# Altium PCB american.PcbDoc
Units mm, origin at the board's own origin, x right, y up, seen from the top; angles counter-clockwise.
Board outline 35 x 24 mm, 2 copper layers (Top Layer, Bottom Layer); 35 components, 19 nets, 74 pads, 16 vias.
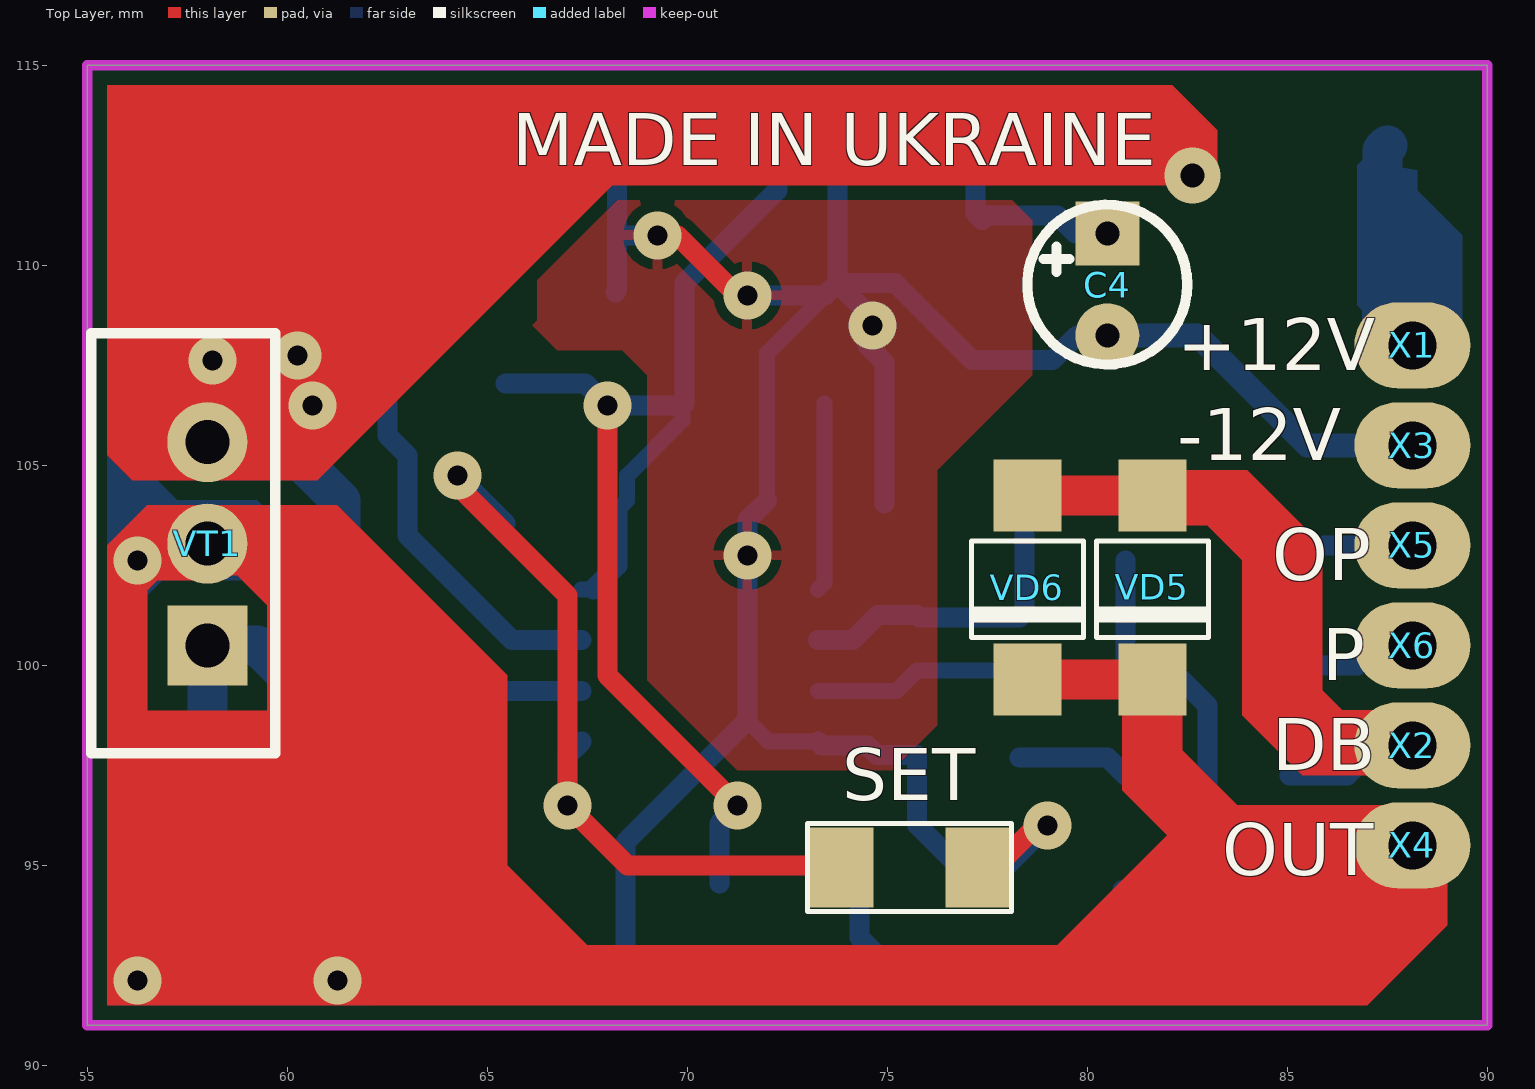
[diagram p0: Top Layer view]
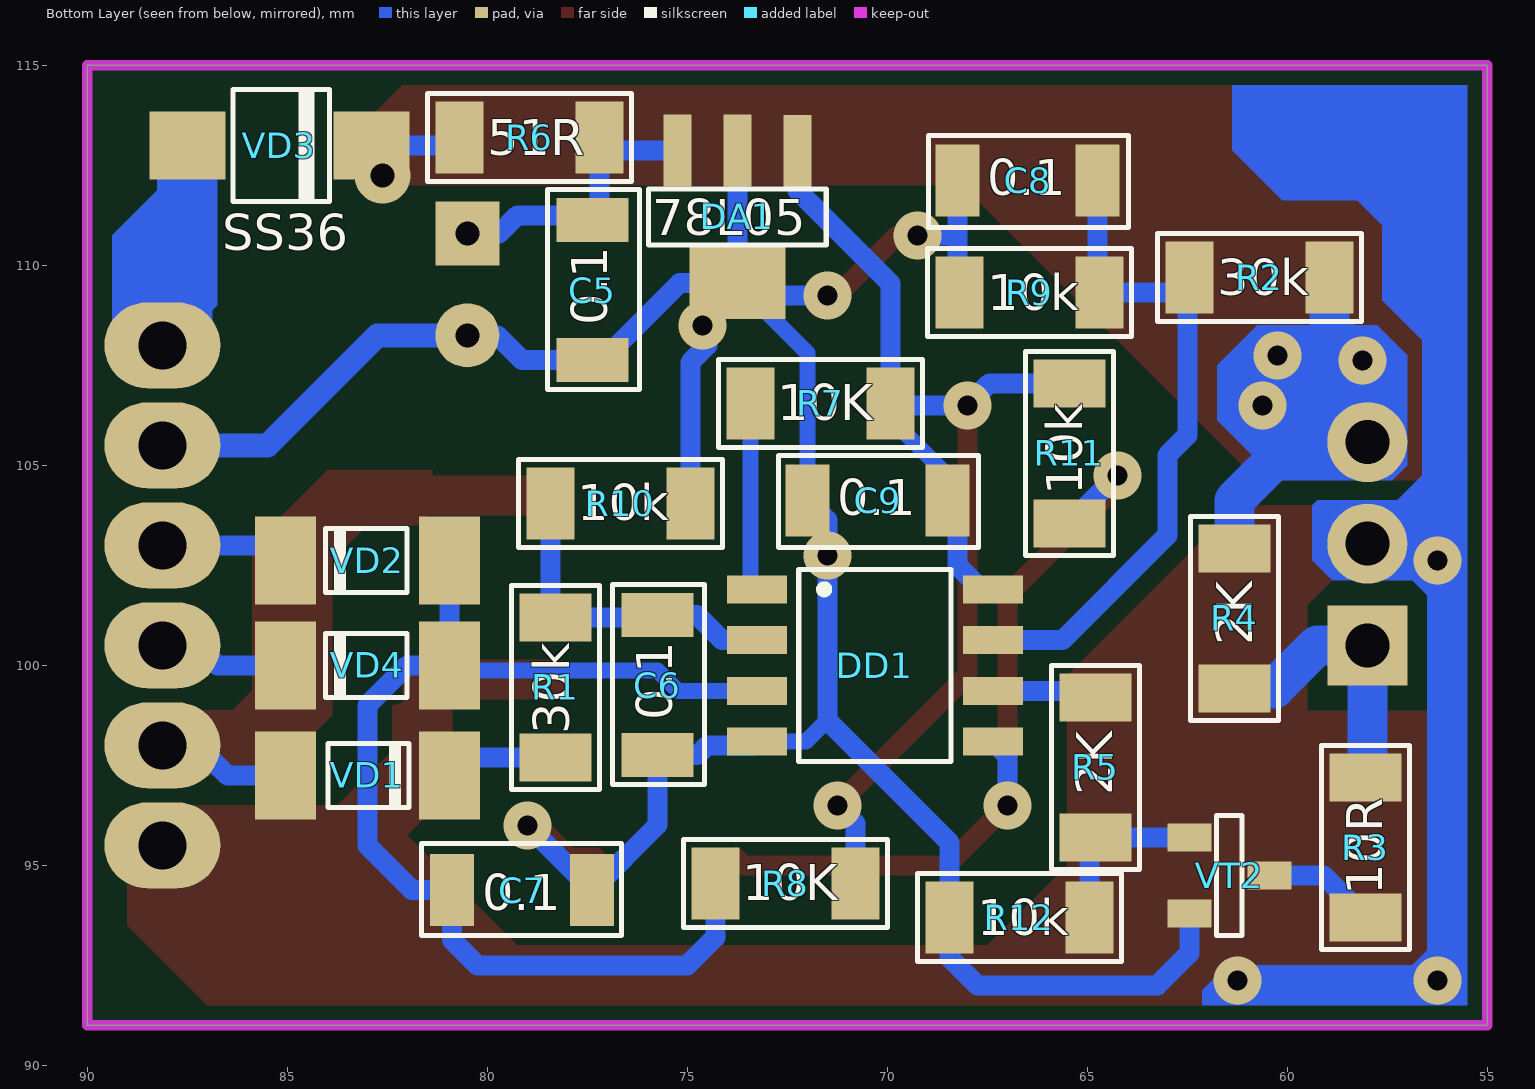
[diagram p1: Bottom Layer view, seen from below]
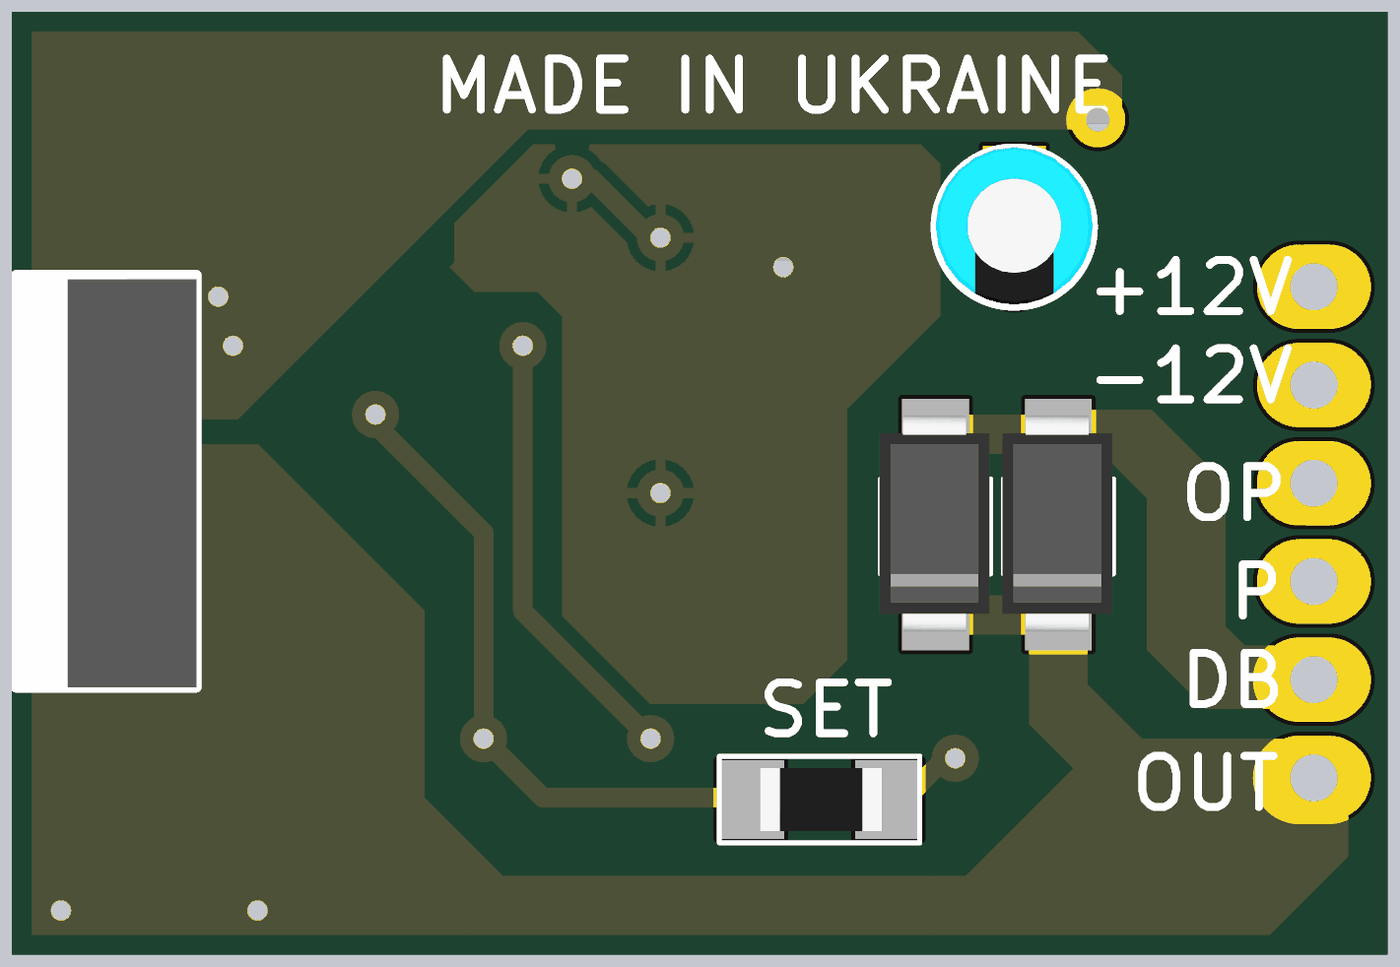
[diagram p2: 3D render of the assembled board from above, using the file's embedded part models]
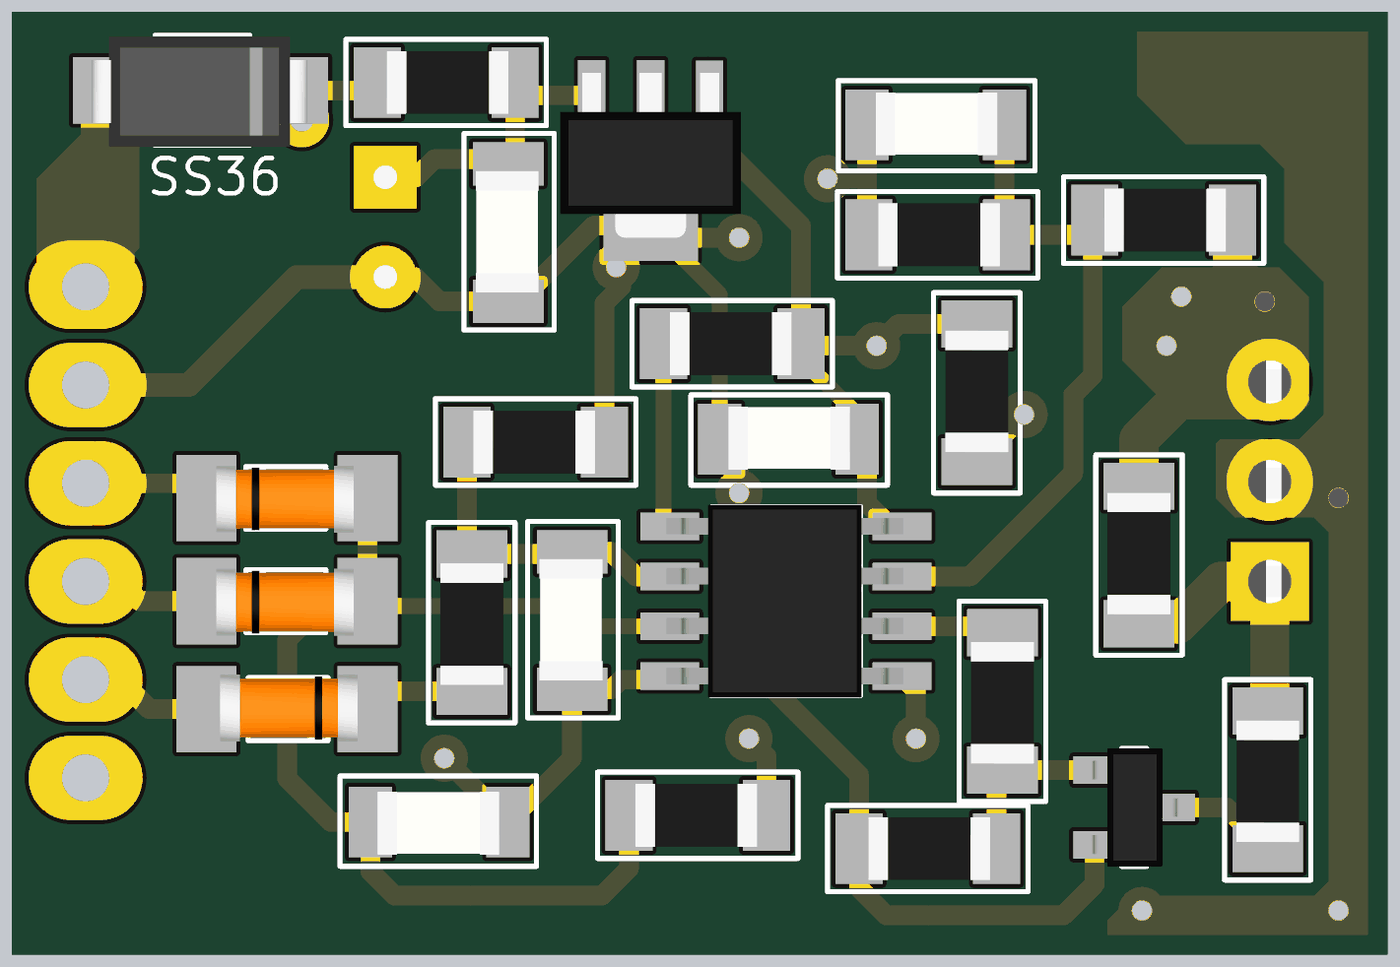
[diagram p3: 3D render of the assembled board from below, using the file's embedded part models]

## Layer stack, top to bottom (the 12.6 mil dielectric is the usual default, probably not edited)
Top Solder: solder mask 0.0102, Solder Resist, Dk 3.5
Top Layer: signal copper 0.0356
Dielectric 1: dielectric 0.32, FR-4, Dk 4.8
Bottom Layer: signal copper 0.0356
Bottom Solder: solder mask 0.0102, Solder Resist, Dk 3.5

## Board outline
55,91 90,91 90,115 55,115

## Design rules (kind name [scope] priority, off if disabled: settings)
Clearance [All] p1: gap=0.254
PolygonConnect [All] p1: connectstyle=Relief reliefconductorwidth=0.254 reliefentries=4 polygonreliefangle="90 Angle" airgapwidth=0.254
RoutingVias [All] p1: holewidth=0.711 width=1.27 viastyle="Through Hole" minholewidth=0.711 minwidth=1.27 maxholewidth=0.711 maxwidth=1.27
SolderMaskExpansion [All] p1: expansion=0.102
Width [All] p1: maxlimit=1 minlimit=0.4 preferedwidth=0.5
29 further rules are at their usual default settings.

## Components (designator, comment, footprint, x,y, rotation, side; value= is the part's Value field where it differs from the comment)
C4 "22.0" 2.54mm 80.5,108.25 r90 top
C5 "0.1" 1206_CAP 78,107.5 r90 bottom
C6 "0.1" 1206_CAP 76.375,97.625 r90 bottom
C7 "0.1" 1206_CAP 77.25,93.75 r0 bottom
C8 "0.1" 1206_CAP 68.375,112.75 r180 bottom
C9 "0.1" 1206_CAP 72.125,104.75 r180 bottom
DA1 "78L05" SOT89 73.75,109.875 r0 bottom
DD1 "ATtiny13A" SO8 72.25,102.5 r180 bottom
R1 "30k" 1206#1 77.5,101 r270 bottom
R2 "30k" 1206#1 62.25,110.5 r180 bottom
R3 "10R" 1206#1 57.25,97 r270 bottom
R4 "2K" 1206#1 62.125,99.625 r90 bottom
R5 "2K" 1206#1 64,99 r270 bottom
R6 "51R" 1206#1 80.5,114 r180 bottom
R7 "10K" 1206#1 70.125,105.75 r0 bottom
R8 "10K" 1206#1 71,93.75 r0 bottom
R9 "10k" 1206#1 68,110.125 r180 bottom
R10 "10k" 1206#1 75.125,103.25 r0 bottom
R11 "10k" 1206#1 66.25,103.75 r90 bottom
R12 "10k" 1206#1 68.25,94.5 r180 bottom
SET "10k" 1206#2 74,95.75 r0 top
VD1 "LL4148" SOD80 84.75,97.25 r180 bottom
VD2 "LL4148" SOD80 81.25,102.625 r0 bottom
VD3 "SS36" SMA(DO-214AC)#1 87.5,113 r180 bottom
VD4 "LL4148" SOD80 81.25,100 r0 bottom
VD5 "SS36" SMA(DO-214AC)#2 81.625,104.25 r270 top
VD6 "SS36" SMA(DO-214AC)#2 78.5,104.25 r270 top
VT1 "IRF9Z34NPBF" TO220 58,100.5 r90 top
VT2 "BC817" SOT23 60.75,94.75 r270 bottom
X1 "CON1" ZL201-1G 88.125,108 r0 top
X2 "CON1" ZL201-1G 88.125,98 r0 top
X3 "CON1" ZL201-1G 88.125,105.5 r0 top
X4 "CON1" ZL201-1G 88.125,95.5 r0 top
X5 "CON1" ZL201-1G 88.125,103 r0 top
X6 "CON1" ZL201-1G 88.125,100.5 r0 top

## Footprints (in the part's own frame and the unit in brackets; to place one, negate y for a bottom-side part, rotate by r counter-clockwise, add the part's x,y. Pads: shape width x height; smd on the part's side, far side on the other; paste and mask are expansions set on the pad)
2.54mm [mm]
  round 1.6 hole 0.6: 1(0,0)
  rect 1.6x1.6 hole 0.6: 2(2.54,0)
  silkscreen extent -0.73,-2 3.27,2, body extent -0.71,-2 3.3,2, height 7.5
1206#1 [mm]
  rect 1.2x1.8 smd: 1(-0.2,-0.8) 2(3.3,-0.8)
  silkscreen extent -1,-1.9 4.1,0.3, body extent 0.04,-1.6 3.14,0, height 0.6
1206#2 [mm]
  rect 1.7x2 smd: 1(-0.2,-0.8) 2(3.3,-0.8)
  silkscreen extent -1,-1.9 4.1,0.3, body extent 0.04,-1.6 3.14,0, height 0.6
1206_CAP [mm]
  rect 1.1x1.8 smd: 1(0.13,-0.628) 2(3.63,-0.628)
  silkscreen extent -0.6,-1.8 4.4,0.5, body extent 0.35,-1.4 3.45,0.2, height 1
SMA(DO-214AC)#1 [mm]
  rect 1.9x1.7 smd: 1(0,0) 2(4.6,0)
  silkscreen extent 1.14,-1.4 3.56,1.4, body extent -0.48,-1.43 5.02,1.37, height 2.31
SMA(DO-214AC)#2 [mm]
  rect 1.8x1.7 smd: 1(0,0) 2(4.6,0)
  silkscreen extent 1.14,-1.4 3.56,1.4, body extent -0.48,-1.43 5.02,1.37, height 2.31
SO8 [mm]
  rect 1.5x0.7 smd: 1(-1.013,-0.6) 2(-1.013,-1.87) 3(-1.013,-3.14) 4(-1.013,-4.41) 5(4.893,-4.41) 6(4.893,-3.14) 7(4.893,-1.87) 8(4.893,-0.6)
  silkscreen extent 0.03,-4.9 3.84,-0.1, body extent -1.1,-4.95 4.93,-0.05, height 1.6
SOD80 [mm]
  rect 1.524x2.2 smd: 1(-0.3,0) 2(3.8,0)
  silkscreen extent 0.76,-0.8 2.79,0.84, body extent 0.05,-0.82 3.55,0.88, height 1.7
SOT23 [mm]
  rect 0.7x1.1 smd: 1(-0.95,-1.7) 2(0.95,-1.7) 3(0,0.3)
  silkscreen extent -1.5,-1.02 1.5,-0.38, body extent -1.5,-2 1.5,0.65, height 1.2
SOT89 [mm]
  rect 0.7x1.8 smd: 1(1.5,-3) 2(0,-3) 3(-1.5,-2.983)
  rect 2.4x1.8 smd: 2(0,0.318)
  silkscreen extent -2.22,-2.03 2.22,-0.64, body extent -2.3,-3.58 2.3,0.63, height 1.6
TO220 [mm]
  rect 2x2 hole 1.1: 1(0,0)
  round 2 hole 1.1: 2(2.54,0) 3(5.08,0)
  silkscreen extent -2.7,-1.7 7.8,2.9, body extent -2.7,-1.7 7.7,2.8, height 18.5
ZL201-1G [mm]
  oval 2.9x2.15 hole 1.2: 1(0,0)

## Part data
C4: library part CAP_POL
C5 C6 C7 C8 C9: library part CAP
DA1: library part 78Lxx
DD1: "1 KB Flash"
R1 R2 R3 R4 R5 R7 R8 R9 R10 R11 R12 SET: library part res_0.25
R6: library part res_0.125
VD3: library part 15MQ040N
VD5 VD6: library part 15MQ040N, "60В, 3А"
VT1: library part IRF4905, "P-Channel -55 V, -17А, 100мОм"
VT2: "N-P-N"

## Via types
v1: diameter 1.2, hole 0.5, Top Layer to Bottom Layer, tented both sides, 15 vias
v2: diameter 1.4, hole 0.6, Top Layer to Bottom Layer, 1 vias

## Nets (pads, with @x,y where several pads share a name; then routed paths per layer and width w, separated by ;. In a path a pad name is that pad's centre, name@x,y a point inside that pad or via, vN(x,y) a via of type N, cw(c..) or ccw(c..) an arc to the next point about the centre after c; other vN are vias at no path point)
+5V: C9.2 DA1.3 DD1.8 R7.1 R8.1 R11.2 | length 31.3
  Top Layer w0.5: v1(68,106.5) 68,99.75 v1(71.25,96.5)
  Bottom Layer w0.4: DD1.8 DD1.8@67.65,101.9 ; C9.2@68.25,103.878 C9.2 68.495,104.745 69.875,106.125 R7.1@69.875,106.5
  Bottom Layer w0.5: R11.2 67.45,107.05 v1(68,106.5) 69.875,106.5 R7.1 69.925,109.55 72.25,111.875 DA1.3 ; DD1.8@67.65,101.9 68.25,102.5 C9.2@68.25,103.878 ; R8.1 70.8,96.05 v1(71.25,96.5)
+12V: R2.2 R4.2 R6.1 VD3.2 VT1.3 | length 41
  Top Layer w1: VT1.3 58,108.25 62.25,112.5 v2@82.625,112.5
  Bottom Layer w0.5: R6.1 80.9,113 VD3.2
  Bottom Layer w1: R2.2 58.95,108.45 58,107.5 VT1.3 59.87,105.58 61.325,104.125 R4.2
  other v1: 60.625,106.5 58.125,107.625 60.25,107.75
  other v2: 82.625,112.25
GND: C4.1 C5.1 C6.1 C7.1 C8.1 C9.1 DA1.2 DD1.4 R9.1 R10.1 R12.1 SET.2 VT2.2 X3.1 | length 74.2
  Top Layer w0.5: v1(69.25,110.75) 69.75,110.75 71.25,109.25 v1(71.5,109.25) ; SET.2@77.3,95.2 77.95,95.2 78.75,96 v1(79,96)
  Bottom Layer w0.4: 71.5,98.625 72.035,98.09 DD1.4 ; C9.1 71.995,107.802 DA1.2@73.442,109.25
  Bottom Layer w0.5: VT2.2 62.45,92.8 63.25,92 67.75,92 68.45,92.7 R12.1 68.45,95.575 71.5,98.625 71.5,103.627 C9.1 ; R9.1 68.245,109.37 68.245,110.75 ; C8.1 68.245,110.75 ; v1(69.25,110.75) 68.245,110.75 ; v1(71.5,109.25) 73.442,109.25 DA1.2@73.75,109.557 ; DD1.4 73.353,98 74.5,98 74.745,97.755 C6.1 75.747,96.01 C7.1 77.38,94.38 v1(79,96) ; DA1.2@73.75,112.875 DA1.2@73.75,109.557 ; R10.1 74.925,107.575 74.5,108 74.5,108.807 DA1.2@73.75,109.557 ; C4.1 79.75,108.25 79.13,107.63 C5.1 77.12,107.63 75.193,109.557 DA1.2@73.75,109.557
  Bottom Layer w0.6: C4.1 82.75,108.25 85.5,105.5 X3.1
  other v1: 71.5,102.75 74.625,108.5
NetC4_2: C4.2 C5.2 DA1.1 R6.2 | length 7.6
  Bottom Layer w0.5: DA1.1 76.875,112.875 R6.2 77.2,111.303 C5.2 77.492,111.25 79.25,111.25 79.71,110.79 C4.2
NetC6_2: C6.2 DD1.2 R1.1 R10.2 | length 8.2
  Bottom Layer w0.5: DD1.2 74.13,100.63 74.755,101.255 C6.2 75.802,101.2 R1.1 78.425,101.325 R10.2
NetC7_2: C7.2 DD1.3 R8.2 VD2.1 VD4.1 | length 28.5
  Bottom Layer w0.4: DD1.3 75.235,99.36 75.75,99.875 VD4.1@80.625,99.875
  Bottom Layer w0.5: R8.2 74.3,93.2 75,92.5 80.25,92.5 80.88,93.13 C7.2 81.878,94.378 83,95.5 83,99 82,100 VD4.1 VD2.1
NetC8_2: C8.2 DD1.7 R2.1 R9.2 | length 17.3
  Bottom Layer w0.5: R2.1 R2.1@62.5,109.65 ; C8.2 64.745,109.37 R9.2 62.825,109.325 R2.1@62.5,109.65 ; DD1.7 65.62,100.63 63,103.25 63,105.25 62.5,105.75 R2.1@62.5,109.65
NetDD1_1: DD1.1 R7.2 | length 4.7
  Bottom Layer w0.4: DD1.1 73.425,102.062 R7.2
NetDD1_5: DD1.5 R11.1 SET.1 | length 20.3
  Top Layer w0.5: v1(64.25,104.75) 64.25,104.5 67,101.75 v1(67,96.5) 68.5,95 73.6,95 SET.1@73.8,95.2
  Bottom Layer w0.5: v1(64.25,104.75) R11.1 ; v1(67,96.5) 67,97.733 DD1.5
NetDD1_6: DD1.6 R5.1 | length 2.6
  Bottom Layer w0.5: R5.1 64.96,99.36 DD1.6
NetR1_2: R1.2 VD1.2 | length 2.8
  Bottom Layer w0.5: R1.2 80.5,97.7 VD1.2
NetR3_1: R3.1 R4.1 VT1.1 | length 7.1
  Bottom Layer w1: R3.1 58,97.25 VT1.1 59.25,100.5 60.325,99.425 R4.1
NetR3_2: R3.2 VT2.3 | length 2.8
  Bottom Layer w0.5: R3.2 59.1,94.75 VT2.3
NetR5_2: R5.2 R12.2 VT2.1 | length 4.3
  Bottom Layer w0.5: VT2.1 64.675,95.7 64.95,95.425 R12.2
NetVD1_1: VD1.1 VD5.1 VD6.1 X2.1 | length 17.4
  Top Layer w1: VD6.1 VD5.1 83.25,104.25 85.125,102.375 85.125,99.25 86.125,98.25 87.875,98.25 X2.1
  Bottom Layer w0.5: VD1.1 86.5,97.25 87.25,98 X2.1
NetVD2_2: VD2.2 X5.1 | length 3.2
  Bottom Layer w0.5: VD2.2 85.425,103 X5.1
NetVD3_1: VD3.1 X1.1 | length 5.4
  Bottom Layer w1: VD3.1 87.375,112.875 87.375,110.5 88.125,109.75 X1.1
NetVD4_2: VD4.2 X6.1 | length 3.3
  Bottom Layer w0.5: VD4.2 86.75,100 87.25,100.5 X6.1
NetVD5_2: VD5.2 VD6.2 VT1.2 X4.1 | length 46.3
  Top Layer w1: VT1.2 59.71,103.04 61.25,101.5 61.25,97 66,92.25 84.875,92.25 X4.1 ; VD6.2 VD5.2 81.625,97.5 83.375,95.75
  other v1: 56.25,92.125 61.25,92.125 56.25,102.625

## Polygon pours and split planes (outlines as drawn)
GND on Top Layer "Top Layer-No Net" (solid, pour order 3): 66.125,109.5 67.375,110.75 67.75,111.125 68.25,111.625 69.875,111.625 78.125,111.625 78.625,111.125 78.625,108.875 78.625,107.25 77.125,105.75 76.25,104.875 76.25,102.375 76.25,98.5 75.25,97.5 75.125,97.375 73.75,97.375 71.25,97.375 69.75,98.875 69,99.625 69,104.75 69,107.25 68.625,107.625 68.375,107.875 67,107.875 66.75,107.875 66.125,108.5 66.25,108.625 66.25,109.625

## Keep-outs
Keep-Out Layer:
  the board outline again, w0.254

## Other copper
Top Layer:
  rectangle net NetVD5_2: 56.125,92.375 61.125,98.875
  rectangle net NetVD5_2: 59.5,91.875 61.75,93.5
  region net +12V: 59,104.625 56.125,104.625 55.5,105.25 55.5,114.5 60.375,114.5
  region net +12V: 83.25,112.125 83.25,113.375 82.125,114.5 59.25,114.5 56.25,111.5 56.25,106 57.625,104.625 60.75,104.625 68.125,112 82.75,112 82.875,111.875
  region net NetVD5_2: 57.875,102.125 56.75,102.125 56.5,101.875 56.5,92.875 56.875,92.5 61.125,92.5 61.75,91.875 61.75,91.5 55.5,91.5 55.5,103 56.5,104 58.375,104
  region net NetVD5_2: 58,104 61.25,104 65.5,99.75 65.5,95 67.5,93 79.25,93 82.75,96.5 88.25,96.5 89,95.75 89,93.5 87,91.5 61.5,91.5 59.5,93.5 59.5,101.5 58.75,102.25 58,102.25
  region net NetVD1_1: 87.875,98.875 86.375,98.875 85.875,99.375 85.875,103 84,104.875 81.375,104.875 81.375,103.875 81.75,103.5 83,103.5 83.875,102.625 83.875,98.75 85.375,97.25 88.25,97.25
  region net NetVD5_2: 80.875,98.875 80.875,96.875 82.625,95.125 84,95.125 84.375,95.5 83.625,95.5 81.625,97.5 81.625,99.125
  region net NetVD5_2: 82.375,99 82.375,97.875 84,96.25 84,95.5 82.75,95.5 81.375,96.875 81.375,99.25
Bottom Layer:
  region net NetVD3_1: 88.25,112.375 88.25,111.875 89.375,110.75 89.375,108.5 88.75,107.875 86.875,107.875 86.875,108.875 86.75,109 86.75,112.5 86.875,112.625
  region net NetVD5_2: 57.625,92.5 61.5,92.5 62.125,91.875 62.125,91.5 57.875,91.5 57.625,91.75
  region net NetVD5_2: 58.5,103.875 57.5,103.875 56.625,104.75 56.625,108.125 57.625,109.125 57.625,111 58.25,111.625 60.125,111.625 61.375,112.875 61.375,114.5 55.5,114.5 55.5,91.5 58.25,91.5 58.25,91.875 57.625,92.5 56.875,92.5 56.5,92.875 56.5,101.75 56.875,102.125 58,102.125
  region net NetVD5_2: 57.125,104.125 59.25,104.125 59.375,104 59.375,102.625 58.875,102.125 56.5,102.125
  region net +12V: 57,105 57.375,104.625 60.25,104.625 61.75,106.125 61.75,107.5 60.75,108.5 57.75,108.5 57,107.75

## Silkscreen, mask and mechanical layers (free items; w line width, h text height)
Top Overlay:
  text "MADE IN UKRAINE" at 65.625,112.5 h1.3
  text "+12V" at 82.25,107.375 h1.3
  text "-12V" at 82.25,105.125 h1.3
  text "OP" at 84.625,102.125 h1.3
  text "P" at 85.875,99.625 h1.3
  text "DB" at 84.625,97.375 h1.3
  text "OUT" at 83.375,94.75 h1.3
